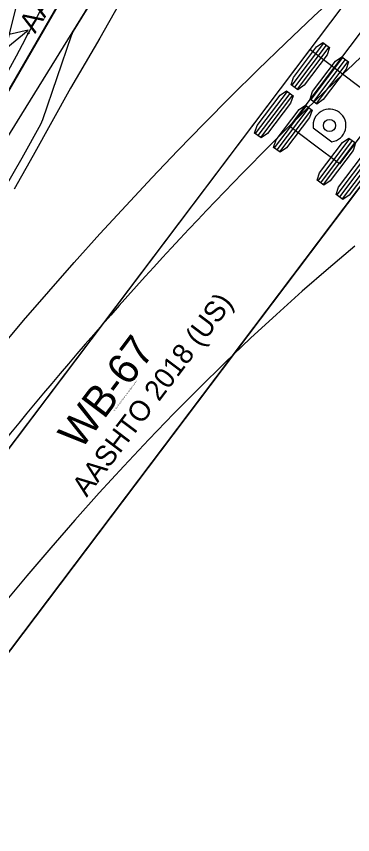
# Model space of a CAD drawing. Extents: x 973688 to 979179, y 703586 to 707602.
# Drawn here: x 973979.1 to 974002.4, y 707214.3 to 707271.1 of the extents above; entities that cross this region are included whole.
import ezdxf

# ---------------------------------------------------------------- set-up
doc = ezdxf.new("R2010")
doc.units = 0
doc.layers.add('0-NPLT', color=7, linetype='Continuous')
doc.layers.add('NO PLOT', color=7, linetype='Continuous')

msp = doc.modelspace()

# ---------------------------------------------------------------- linework, layer by layer
at = {"layer": '0-NPLT'}
for p, q in [((974000.434, 707269.22), (973998.226, 707266.293)), ((974000.434, 707269.22), (973998.226, 707266.293)), ((974000.617, 707269.082), (973998.409, 707266.155)), ((974000.617, 707269.082), (973998.409, 707266.155)), ((974000.8, 707268.944), (973998.592, 707266.017)), ((974000.8, 707268.944), (973998.592, 707266.017)), ((974001.752, 707268.226), (973999.543, 707265.299)), ((974001.752, 707268.226), (973999.543, 707265.299)), ((974001.934, 707268.088), (973999.726, 707265.161)), ((974001.934, 707268.088), (973999.726, 707265.161)), ((974002.117, 707267.95), (973999.909, 707265.023)), ((974002.117, 707267.95), (973999.909, 707265.023)), ((973997.905, 707265.868), (973995.696, 707262.941)), ((973997.905, 707265.868), (973995.696, 707262.941)), ((973998.087, 707265.73), (973995.879, 707262.803)), ((973998.087, 707265.73), (973995.879, 707262.803)), ((973998.27, 707265.592), (973996.062, 707262.665)), ((973998.27, 707265.592), (973996.062, 707262.665)), ((973999.222, 707264.874), (973997.013, 707261.947)), ((973999.222, 707264.874), (973997.013, 707261.947)), ((973999.404, 707264.736), (973997.196, 707261.809)), ((973999.404, 707264.736), (973997.196, 707261.809)), ((973999.587, 707264.598), (973997.379, 707261.671)), ((973999.587, 707264.598), (973997.379, 707261.671)), ((973999.712, 707263.336), (974001.002, 707262.363)), ((973999.712, 707263.336), (974001.002, 707262.363)), ((974002.241, 707262.595), (974000.033, 707259.668)), ((974002.241, 707262.595), (974000.033, 707259.668)), ((974002.424, 707262.457), (974000.216, 707259.53)), ((974002.424, 707262.457), (974000.216, 707259.53)), ((974002.607, 707262.319), (974000.399, 707259.392)), ((974002.607, 707262.319), (974000.399, 707259.392)), ((974003.559, 707261.601), (974001.35, 707258.674)), ((974003.559, 707261.601), (974001.35, 707258.674)), ((974003.741, 707261.463), (974001.533, 707258.536)), ((974003.741, 707261.463), (974001.533, 707258.536)), ((974003.924, 707261.325), (974001.716, 707258.398)), ((974003.924, 707261.325), (974001.716, 707258.398))]:
    msp.add_line(p, q, dxfattribs=at)
for points in [[(974067.075, 707344.234), (973974.349, 707221.338), (973967.564, 707226.458), (973967.646, 707226.567), (973967.646, 707226.567)], [(974067.075, 707344.234), (973974.349, 707221.338), (973967.564, 707226.458), (973967.646, 707226.567), (973967.646, 707226.567)], [(973967.646, 707226.567), (974034.216, 707314.792)], [(973967.646, 707226.567), (974034.216, 707314.792)], [(973992.958, 707302.175), (973992.939, 707302.186), (973992.902, 707302.126), (973989.92, 707297.307), (973965.088, 707257.177), (973968.703, 707254.94), (973972.317, 707252.704), (973997.148, 707292.835), (974000.129, 707297.654), (974000.166, 707297.714), (974000.148, 707297.726)], [(973992.958, 707302.175), (973992.939, 707302.186), (973992.902, 707302.126), (973989.92, 707297.307), (973965.088, 707257.177), (973968.703, 707254.94), (973972.317, 707252.704), (973997.148, 707292.835), (974000.129, 707297.654), (974000.166, 707297.714), (974000.148, 707297.726)], [(974003.013, 707302.3), (973983.059, 707270.041), (973982.924, 707269.731), (973980.931, 707263.883), (973980.789, 707263.578), (973979.494, 707261.232), (973978.152, 707258.904)], [(974003.013, 707302.3), (973983.059, 707270.041), (973982.924, 707269.731), (973980.931, 707263.883), (973980.789, 707263.578), (973979.494, 707261.232), (973978.152, 707258.904)], [(973932.491, 707180.821), (973962.343, 707226.134), (973963.82, 707228.324), (973965.306, 707230.478), (973967.953, 707234.203), (973973.056, 707241.95), (973974.504, 707243.785), (973976.189, 707245.858), (973977.895, 707247.914), (973979.621, 707249.954), (973981.367, 707251.978), (973983.134, 707253.984), (973984.922, 707255.974), (973986.73, 707257.947), (973988.522, 707259.864), (973990.329, 707261.76), (973992.157, 707263.641), (973994.006, 707265.508), (973995.877, 707267.36), (973997.791, 707269.218), (973999.751, 707271.083), (974001.735, 707272.934), (974003.743, 707274.769)], [(973932.491, 707180.821), (973962.343, 707226.134), (973963.82, 707228.324), (973965.306, 707230.478), (973967.953, 707234.203), (973973.056, 707241.95), (973974.504, 707243.785), (973976.189, 707245.858), (973977.895, 707247.914), (973979.621, 707249.954), (973981.367, 707251.978), (973983.134, 707253.984), (973984.922, 707255.974), (973986.73, 707257.947), (973988.522, 707259.864), (973990.329, 707261.76), (973992.157, 707263.641), (973994.006, 707265.508), (973995.877, 707267.36), (973997.791, 707269.218), (973999.751, 707271.083), (974001.735, 707272.934), (974003.743, 707274.769)], [(973981.39, 707272.524), (973981.225, 707272.234), (973981.061, 707271.944), (973980.899, 707271.653), (973980.738, 707271.361), (973980.578, 707271.068), (973980.42, 707270.775), (973980.263, 707270.481), (973980.107, 707270.186), (973979.953, 707269.891)], [(973981.39, 707272.524), (973981.225, 707272.234), (973981.061, 707271.944), (973980.899, 707271.653), (973980.738, 707271.361), (973980.578, 707271.068), (973980.42, 707270.775), (973980.263, 707270.481), (973980.107, 707270.186), (973979.953, 707269.891)], [(974008.471, 707268.876), (974007.924, 707269.289), (974007.78, 707269.1), (974001.538, 707260.829), (973999.81, 707262.133), (973998.082, 707263.437), (974004.324, 707271.708), (974004.466, 707271.899), (974003.919, 707272.312)], [(974008.471, 707268.876), (974007.924, 707269.289), (974007.78, 707269.1), (974001.538, 707260.829), (973999.81, 707262.133), (973998.082, 707263.437), (974004.324, 707271.708), (974004.466, 707271.899), (974003.919, 707272.312)], [(973986.219, 707271.858), (973984.918, 707269.55), (973982.884, 707266.085), (973980.298, 707261.413), (973978.974, 707259.089)], [(973986.219, 707271.858), (973984.918, 707269.55), (973982.884, 707266.085), (973980.298, 707261.413), (973978.974, 707259.089)], [(973978.397, 707268.846), (973979.942, 707270.116), (973978.623, 707269.821), (973977.57, 707270.668), (973978.397, 707268.846)], [(973978.397, 707268.846), (973979.942, 707270.116), (973978.623, 707269.821), (973977.57, 707270.668), (973978.397, 707268.846)], [(973974.373, 707221.408), (973974.391, 707221.395), (973974.433, 707221.451), (973977.848, 707225.975), (974006.275, 707263.644), (974002.882, 707266.204), (973999.49, 707268.764), (973971.063, 707231.095), (973967.65, 707226.571), (973967.607, 707226.514), (973967.624, 707226.501)], [(973974.373, 707221.408), (973974.391, 707221.395), (973974.433, 707221.451), (973977.848, 707225.975), (974006.275, 707263.644), (974002.882, 707266.204), (973999.49, 707268.764), (973971.063, 707231.095), (973967.65, 707226.571), (973967.607, 707226.514), (973967.624, 707226.501)], [(974002.6, 707255.116), (974000.766, 707253.572), (973998.953, 707251.996), (973997.161, 707250.388), (973995.374, 707248.736), (973993.577, 707247.022), (973991.8, 707245.277), (973990.042, 707243.501), (973988.303, 707241.694), (973986.582, 707239.859), (973984.878, 707237.996), (973983.19, 707236.106), (973981.518, 707234.191), (973979.86, 707232.25), (973978.228, 707230.304), (973976.634, 707228.366), (973973.469, 707224.427), (973970.327, 707220.403), (973967.161, 707216.239), (973964.044, 707212.029)], [(974002.6, 707255.116), (974000.766, 707253.572), (973998.953, 707251.996), (973997.161, 707250.388), (973995.374, 707248.736), (973993.577, 707247.022), (973991.8, 707245.277), (973990.042, 707243.501), (973988.303, 707241.694), (973986.582, 707239.859), (973984.878, 707237.996), (973983.19, 707236.106), (973981.518, 707234.191), (973979.86, 707232.25), (973978.228, 707230.304), (973976.634, 707228.366), (973973.469, 707224.427), (973970.327, 707220.403), (973967.161, 707216.239), (973964.044, 707212.029)]]:
    msp.add_lwpolyline(points, dxfattribs=at)
for points in [[(973978.397, 707268.846), (973979.942, 707270.116), (973978.623, 707269.821), (973977.57, 707270.668)], [(973978.397, 707268.846), (973979.942, 707270.116), (973978.623, 707269.821), (973977.57, 707270.668)], [(974000.389, 707269.254), (974000.846, 707268.91), (974000.674, 707268.396), (973999.084, 707266.289), (973998.637, 707265.983), (973998.18, 707266.328), (973998.352, 707266.841), (973999.942, 707268.948)], [(974000.389, 707269.254), (974000.846, 707268.91), (974000.674, 707268.396), (973999.084, 707266.289), (973998.637, 707265.983), (973998.18, 707266.328), (973998.352, 707266.841), (973999.942, 707268.948)], [(974001.706, 707268.26), (974002.163, 707267.916), (974001.991, 707267.402), (974000.401, 707265.295), (973999.954, 707264.989), (973999.497, 707265.334), (973999.669, 707265.847), (974001.259, 707267.955)], [(974001.706, 707268.26), (974002.163, 707267.916), (974001.991, 707267.402), (974000.401, 707265.295), (973999.954, 707264.989), (973999.497, 707265.334), (973999.669, 707265.847), (974001.259, 707267.955)], [(973997.859, 707265.902), (973998.316, 707265.557), (973998.144, 707265.044), (973996.554, 707262.936), (973996.107, 707262.631), (973995.65, 707262.975), (973995.822, 707263.489), (973997.412, 707265.596)], [(973997.859, 707265.902), (973998.316, 707265.557), (973998.144, 707265.044), (973996.554, 707262.936), (973996.107, 707262.631), (973995.65, 707262.975), (973995.822, 707263.489), (973997.412, 707265.596)], [(973999.176, 707264.908), (973999.633, 707264.563), (973999.461, 707264.05), (973997.871, 707261.943), (973997.424, 707261.637), (973996.967, 707261.981), (973997.139, 707262.495), (973998.729, 707264.602)], [(973999.176, 707264.908), (973999.633, 707264.563), (973999.461, 707264.05), (973997.871, 707261.943), (973997.424, 707261.637), (973996.967, 707261.981), (973997.139, 707262.495), (973998.729, 707264.602)], [(974002.196, 707262.629), (974002.653, 707262.284), (974002.481, 707261.771), (974000.891, 707259.664), (974000.444, 707259.358), (973999.987, 707259.702), (974000.159, 707260.216), (974001.749, 707262.323)], [(974002.196, 707262.629), (974002.653, 707262.284), (974002.481, 707261.771), (974000.891, 707259.664), (974000.444, 707259.358), (973999.987, 707259.702), (974000.159, 707260.216), (974001.749, 707262.323)], [(974003.513, 707261.635), (974003.97, 707261.29), (974003.798, 707260.777), (974002.208, 707258.67), (974001.761, 707258.364), (974001.304, 707258.708), (974001.476, 707259.222), (974003.066, 707261.329)], [(974003.513, 707261.635), (974003.97, 707261.29), (974003.798, 707260.777), (974002.208, 707258.67), (974001.761, 707258.364), (974001.304, 707258.708), (974001.476, 707259.222), (974003.066, 707261.329)]]:
    msp.add_lwpolyline(points, close=True, dxfattribs=at)
for centre, radius in [((973979.953, 707269.891), 0.0417), ((973979.953, 707269.891), 0.0417), ((973979.953, 707269.891), 0.0417), ((973979.953, 707269.891), 0.0417), ((974000.841, 707263.499), 0.424), ((974000.841, 707263.499), 0.424)]:
    msp.add_circle(centre, radius, dxfattribs=at)
for centre, radius, start, end in [((974170.093, 707224.287), 196.807, 152.83657, 166.91405), ((974170.093, 707224.287), 196.807, 152.83657, 166.91405), ((974185.202, 707074.23), 266.14, 130.08412, 142.42531), ((974185.202, 707074.23), 266.14, 130.08412, 142.42531), ((973771.826, 707378.695), 234.852, 318.71735, 332.40041), ((973771.826, 707378.695), 234.852, 318.71735, 332.40041), ((974000.844, 707263.495), 1.143, 277.9598, 187.9598), ((974000.844, 707263.495), 1.143, 277.9598, 187.9598)]:
    msp.add_arc(centre, radius, start, end, dxfattribs=at)
at = {"layer": 'NO PLOT'}
for points in [[(973990.385, 707286.366), (973973.357, 707256.874)], [(973978.433, 707282.63), (973978.414, 707282.64), (973978.379, 707282.579), (973975.542, 707277.673), (973951.926, 707236.816), (973955.605, 707234.689), (973959.285, 707232.562), (973982.901, 707273.419), (973985.736, 707278.326), (973985.772, 707278.387), (973985.753, 707278.398)]]:
    msp.add_lwpolyline(points, dxfattribs=at)
msp.add_arc((974179.595, 707212.24), 213.339, 144.72191, 165.04007, dxfattribs=at)

# ---------------------------------------------------------------- texts
at = {"layer": '0-NPLT'}
for s, height, rotation, p in [('AASHTO 2018 (US)', 1.41667, 58.2526, (973980.426, 707269.835)), ('AASHTO 2018 (US)', 1.41667, 58.2526, (973980.426, 707269.835)), ('AASHTO 2018 (US)', 1.41667, 52.9598, (973984.004, 707237.648)), ('AASHTO 2018 (US)', 1.41667, 52.9598, (973984.004, 707237.648)), ('WB-67', 2.125, 52.9598, (973983.583, 707240.913)), ('WB-67', 2.125, 52.9598, (973983.583, 707240.913)), ('(c) 2021 Transoft Solutions, Inc. All rights reserved.', 0.085, 52.9598, (973985.91, 707243.643)), ('(c) 2021 Transoft Solutions, Inc. All rights reserved.', 0.085, 52.9598, (973985.91, 707243.643))]:
    msp.add_text(s, height=height, rotation=rotation, dxfattribs=at).set_placement(p)

doc.saveas('drawing.dxf')
